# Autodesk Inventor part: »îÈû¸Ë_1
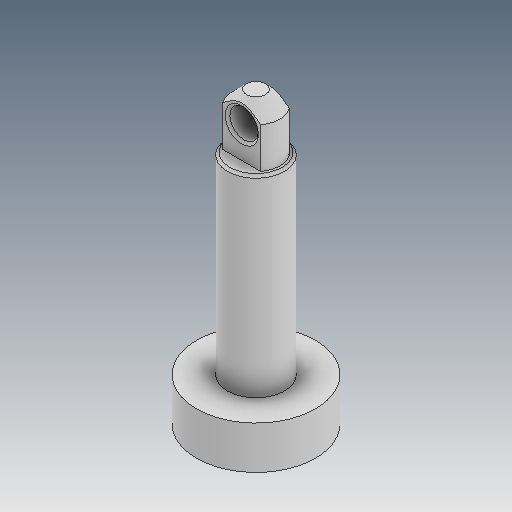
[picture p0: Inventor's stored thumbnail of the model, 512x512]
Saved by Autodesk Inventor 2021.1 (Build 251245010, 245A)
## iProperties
Created: 2019-04
Part Number: »îÈû¸Ë_1
Material: Ogólny
Document SubType Name: Modeling
Designer: user
Density: 1 g/cm^3
Appearance: Domyślna
Author: user
Revision Number: ÈÎºÎ
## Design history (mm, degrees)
feature "ÊäÈë1"
node "Bryła1"
